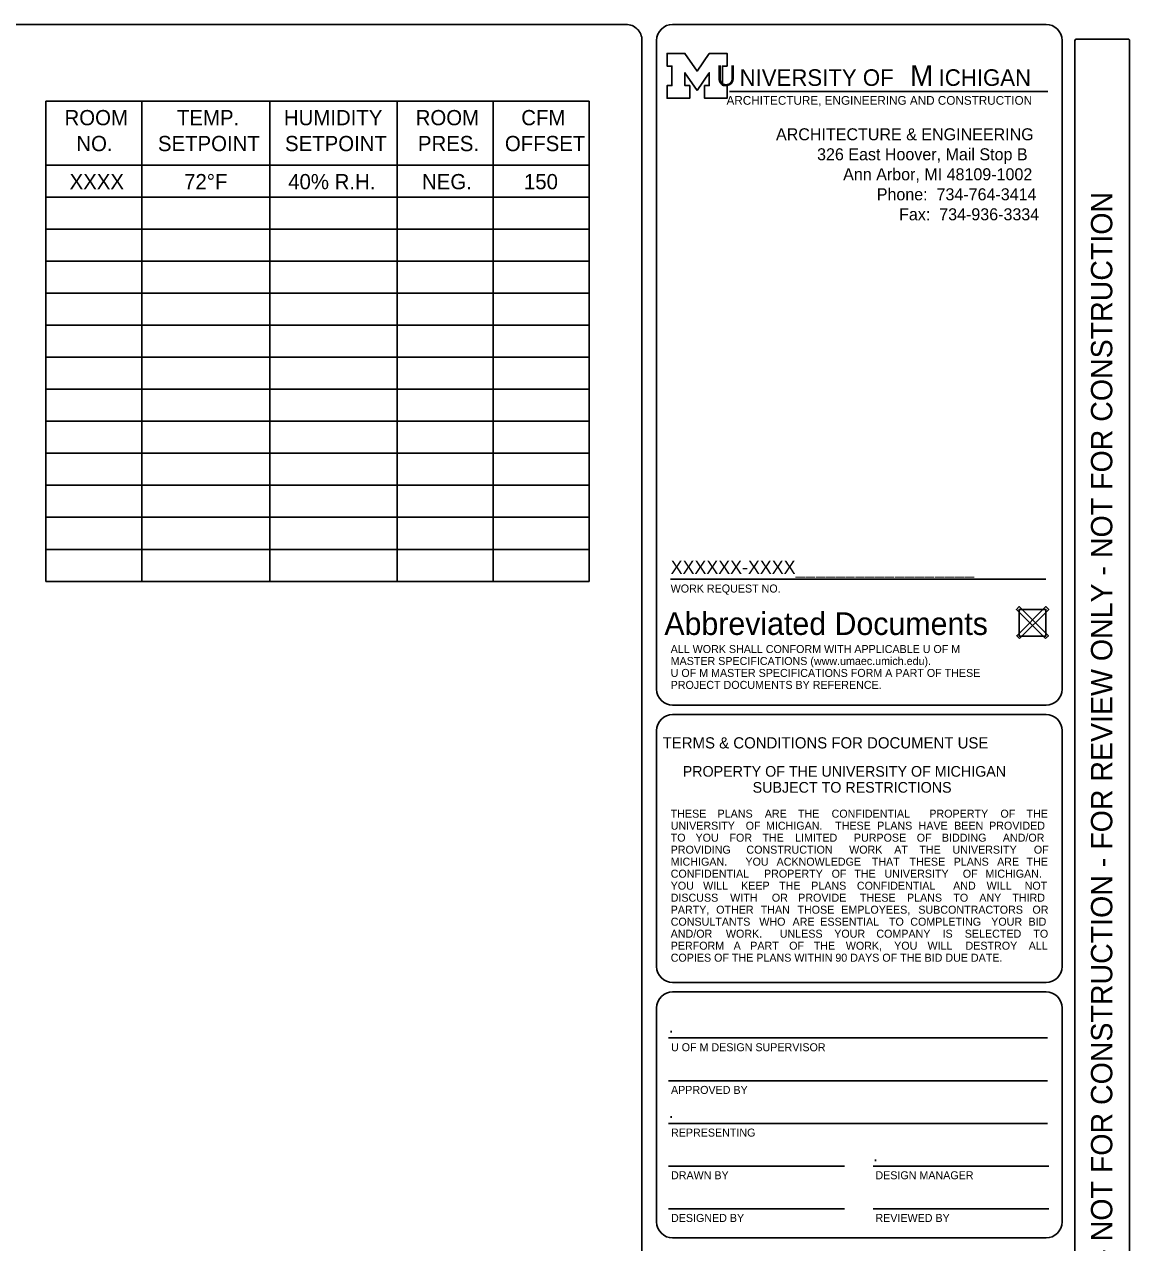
# Model space of a CAD drawing. Extents: x 0 to 567, y 1 to 184.
# Drawn here: x 498.1 to 567.1, y 107.6 to 183.7 of the extents above; entities that cross this region are included whole.
import ezdxf

# ---------------------------------------------------------------- set-up
doc = ezdxf.new("R2010")
doc.units = 0
for name, color, linetype in [('Default', 7, 'Continuous'), ('G-ANNO-CELL', 7, 'Continuous'), ('G-ANNO-LOGO', 7, 'Continuous'), ('G-ANNO-PROJ', 7, 'Continuous'), ('G-ANNO-PROJ (Construction)', 7, 'Continuous'), ('G-ANNO-TTLB', 7, 'Continuous'), ('G-DETL-LINE', 7, 'Continuous')]:
    doc.layers.add(name, color=color, linetype=linetype)

# ---------------------------------------------------------------- blocks, each defined once
blk = doc.blocks.new('POINT_DISPLAY')
at = {"layer": 'Default'}
blk.add_line((0, 0), (0, 0), dxfattribs=at)

msp = doc.modelspace()

# ---------------------------------------------------------------- linework, layer by layer
at = {"layer": 'G-ANNO-LOGO'}
for p, q in [((538.244, 181.132), (538.244, 181.923)), ((538.244, 181.923), (539.359, 181.923)), ((539.359, 181.923), (540.118, 180.822)), ((540.118, 180.822), (540.878, 181.923)), ((540.878, 181.923), (541.993, 181.923)), ((541.993, 181.923), (541.993, 181.132)), ((538.538, 181.132), (538.244, 181.132)), ((538.538, 179.908), (538.538, 181.132)), ((540.118, 179.614), (539.359, 180.714)), ((539.359, 180.714), (539.359, 179.908)), ((540.878, 180.714), (540.118, 179.614)), ((540.878, 179.908), (540.878, 180.714)), ((541.993, 181.132), (541.699, 181.132)), ((541.699, 181.132), (541.699, 179.936)), ((538.244, 179.118), (538.244, 179.908)), ((538.244, 179.908), (538.538, 179.908)), ((539.359, 179.908), (539.654, 179.908)), ((539.654, 179.908), (539.654, 179.118)), ((540.583, 179.118), (540.583, 179.908)), ((540.583, 179.908), (540.878, 179.908)), ((541.699, 179.936), (541.768, 179.908)), ((541.768, 179.908), (541.993, 179.908)), ((541.993, 179.908), (541.993, 179.118)), ((539.654, 179.118), (538.244, 179.118)), ((541.993, 179.118), (540.583, 179.118)), ((542.136, 179.549), (562.029, 179.549))]:
    msp.add_line(p, q, dxfattribs=at)
msp.add_lwpolyline([(540.118, 179.614), (539.359, 180.714), (539.359, 179.908), (539.654, 179.908), (539.654, 179.118), (538.244, 179.118), (538.244, 179.908), (538.538, 179.908), (538.538, 181.132), (538.244, 181.132), (538.244, 181.923), (539.359, 181.923), (540.118, 180.822), (540.878, 181.923), (541.993, 181.923), (541.993, 181.132), (541.699, 181.132), (541.699, 179.936), (541.768, 179.908), (541.993, 179.908), (541.993, 179.118), (540.583, 179.118), (540.583, 179.908), (540.878, 179.908), (540.878, 180.714)], close=True, dxfattribs=at)
at = {"layer": 'G-ANNO-PROJ'}
msp.add_line((561.911, 149.066), (538.463, 149.066), dxfattribs=at)
for points in [[(561.894, 145.354), (560.07, 147.178), (560.244, 147.352), (562.068, 145.528)], [(561.894, 145.354), (560.07, 147.178), (560.244, 147.352), (562.068, 145.528)], [(560.261, 145.354), (562.086, 147.178), (561.911, 147.352), (560.087, 145.528)], [(560.261, 145.354), (562.086, 147.178), (561.911, 147.352), (560.087, 145.528)], [(560.244, 145.511), (561.911, 145.511), (561.911, 147.178), (560.244, 147.178)]]:
    msp.add_lwpolyline(points, close=True, dxfattribs=at)
at = {"layer": 'G-ANNO-TTLB'}
for p, q in [((562.004, 120.398), (538.338, 120.398)), ((562.004, 117.731), (538.338, 117.731)), ((562.004, 115.064), (538.338, 115.064)), ((549.317, 112.398), (538.338, 112.398)), ((562.09, 112.398), (551.112, 112.398)), ((549.317, 109.731), (538.338, 109.731)), ((562.09, 109.731), (551.112, 109.731))]:
    msp.add_line(p, q, dxfattribs=at)
for points in [[(291.922, 183.734), (535.671, 183.735)], [(538.588, 183.737), (561.921, 183.737)], [(536.671, 182.735), (536.671, 2.735)], [(537.588, 142.191), (537.588, 182.737)], [(562.921, 182.737), (562.921, 142.191)], [(563.729, 2.735), (563.729, 182.734)], [(563.813, 182.818), (567.062, 182.818)], [(567.146, 182.735), (567.146, 2.735)], [(561.921, 141.191), (538.588, 141.191)], [(561.921, 140.608), (538.588, 140.608)], [(537.588, 139.608), (537.588, 124.861)], [(562.921, 124.861), (562.921, 139.608)], [(538.588, 123.861), (561.921, 123.861)], [(561.921, 123.278), (538.588, 123.278)], [(537.588, 122.278), (537.588, 108.904)], [(562.921, 108.904), (562.921, 122.278)], [(538.588, 107.904), (561.921, 107.904)]]:
    msp.add_lwpolyline(points, dxfattribs=at)
for centre, radius, start, end in [((535.671, 182.735), 1, 360, 90.00008), ((538.588, 182.737), 1, 90, 180), ((561.921, 182.737), 1, 0, 90), ((563.813, 182.734), 0.0833, 90.00008, 180), ((567.062, 182.735), 0.0833, 360, 90.00007), ((538.588, 142.191), 1, 180, 270), ((561.921, 142.191), 1, 270, 360), ((538.588, 139.608), 1, 90, 180), ((561.921, 139.608), 1, 360, 90), ((538.588, 124.861), 1, 180.00005, 270.00005), ((561.921, 124.861), 1, 270.00005, 0.00005), ((538.588, 122.278), 1, 90, 180), ((561.921, 122.278), 1, 360, 90), ((538.588, 108.904), 1, 180.00005, 270.00005), ((561.921, 108.904), 1, 270.00005, 0.00005)]:
    msp.add_arc(centre, radius, start, end, dxfattribs=at)
at = {"layer": 'G-DETL-LINE'}
for p, q in [((499.423, 178.933), (533.367, 178.933)), ((499.423, 178.933), (499.423, 148.933)), ((505.423, 178.933), (505.423, 148.933)), ((513.423, 178.933), (513.423, 148.933)), ((521.367, 178.933), (521.367, 148.933)), ((527.367, 178.933), (527.367, 148.933)), ((533.367, 178.933), (533.367, 148.933)), ((499.423, 174.933), (521.367, 174.933)), ((521.367, 174.933), (533.367, 174.933)), ((499.423, 172.933), (521.367, 172.933)), ((521.367, 172.933), (533.367, 172.933)), ((499.423, 170.933), (521.367, 170.933)), ((521.367, 170.933), (533.367, 170.933)), ((499.423, 168.933), (521.367, 168.933)), ((521.367, 168.933), (533.367, 168.933)), ((499.423, 166.933), (521.367, 166.933)), ((521.367, 166.933), (533.367, 166.933)), ((499.423, 164.933), (521.367, 164.933)), ((521.367, 164.933), (533.367, 164.933)), ((499.423, 162.933), (521.367, 162.933)), ((521.367, 162.933), (533.367, 162.933)), ((499.423, 160.933), (521.367, 160.933)), ((521.367, 160.933), (533.367, 160.933)), ((499.423, 158.933), (521.367, 158.933)), ((521.367, 158.933), (533.367, 158.933)), ((499.423, 156.933), (521.367, 156.933)), ((521.367, 156.933), (533.367, 156.933)), ((499.423, 154.933), (521.367, 154.933)), ((521.367, 154.933), (533.367, 154.933)), ((499.423, 152.933), (521.367, 152.933)), ((521.367, 152.933), (533.367, 152.933)), ((499.423, 150.933), (521.367, 150.933)), ((521.367, 150.933), (533.367, 150.933)), ((499.423, 148.933), (533.367, 148.933))]:
    msp.add_line(p, q, dxfattribs=at)

# ---------------------------------------------------------------- block references
at = {"layer": 'G-ANNO-PROJ (Construction)'}
msp.add_blockref('POINT_DISPLAY', (538.531, 149.066), dxfattribs=at)

# ---------------------------------------------------------------- texts
at = {"layer": 'G-ANNO-CELL'}
msp.add_text('FOR REVIEW ONLY - NOT FOR CONSTRUCTION - FOR REVIEW ONLY - NOT FOR CONSTRUCTION - FOR REVIEW ONLY - NOT FOR CONSTRUCTION - FOR REVIEW ONLY - NOT FOR CONSTRUCTION', height=1.333333, rotation=90, dxfattribs=at).set_placement((566.063, 4.083))
at = {"layer": 'G-ANNO-LOGO'}
for s, height, p in [('U', 1.285, (541.31, 179.893)), ('NIVERSITY OF', 1.03676, (542.77, 179.893)), ('M', 1.285, (553.433, 179.893)), ('ICHIGAN', 1.0368, (555.208, 179.893)), ('ARCHITECTURE, ENGINEERING AND CONSTRUCTION', 0.54688, (541.955, 178.713)), ('ARCHITECTURE & ENGINEERING', 0.75, (545.046, 176.493)), ('326 East Hoover, Mail Stop B', 0.75, (547.613, 175.243)), ('Ann Arbor, MI 48109-1002', 0.75, (549.243, 173.993)), ('Phone:  734-764-3414', 0.75, (551.343, 172.743)), ('Fax:  734-936-3334', 0.75, (552.739, 171.493))]:
    msp.add_text(s, height=height, dxfattribs=at).set_placement(p)
at = {"layer": 'G-ANNO-PROJ'}
for s, height, p in [('XXXXXX-XXXX__________________', 0.83332, (538.463, 149.399)), ('WORK REQUEST NO.', 0.5, (538.463, 148.233)), ('Abbreviated Documents', 1.41667, (538.069, 145.582)), ('ALL WORK SHALL CONFORM WITH APPLICABLE U OF M ', 0.5, (538.463, 144.453)), ('MASTER SPECIFICATIONS (www.umaec.umich.edu).', 0.5, (538.463, 143.706)), ('U OF M MASTER SPECIFICATIONS FORM A PART OF THESE ', 0.5, (538.463, 142.959)), ('PROJECT DOCUMENTS BY REFERENCE.', 0.5, (538.463, 142.212)), ('TERMS & CONDITIONS FOR DOCUMENT USE', 0.69894, (537.963, 138.491)), ('PROPERTY OF THE UNIVERSITY OF MICHIGAN ', 0.66667, (539.216, 136.726)), ('SUBJECT TO RESTRICTIONS', 0.66667, (543.586, 135.726)), ('THESE ', 0.5, (538.465, 134.165)), ('PLANS ', 0.5, (541.396, 134.165)), ('ARE ', 0.5, (544.346, 134.165)), ('THE ', 0.5, (546.42, 134.165)), ('CONFIDENTIAL ', 0.5, (548.52, 134.165)), ('PROPERTY ', 0.5, (554.628, 134.165)), ('OF ', 0.5, (559.072, 134.165)), ('THE ', 0.5, (560.703, 134.165)), ('UNIVERSITY ', 0.5, (538.465, 133.415)), ('OF ', 0.5, (543.152, 133.415)), ('MICHIGAN. ', 0.5, (544.421, 133.415)), ('THESE ', 0.5, (548.741, 133.415)), ('PLANS ', 0.5, (551.372, 133.415)), ('HAVE ', 0.5, (553.958, 133.415)), ('BEEN ', 0.5, (556.179, 133.415)), ('PROVIDED ', 0.5, (558.363, 133.415)), ('TO ', 0.5, (538.465, 132.665)), ('YOU ', 0.5, (540.016, 132.665)), ('FOR ', 0.5, (542.138, 132.665)), ('THE ', 0.5, (544.197, 132.665)), ('LIMITED ', 0.5, (546.237, 132.665)), ('PURPOSE ', 0.5, (549.913, 132.665)), ('OF ', 0.5, (553.842, 132.665)), ('BIDDING ', 0.5, (555.413, 132.665)), ('AND/OR ', 0.5, (559.22, 132.665)), ('PROVIDING ', 0.5, (538.465, 131.915)), ('CONSTRUCTION ', 0.5, (543.197, 131.915)), ('WORK ', 0.5, (549.616, 131.915)), ('AT ', 0.5, (552.435, 131.915)), ('THE ', 0.5, (554.005, 131.915)), ('UNIVERSITY ', 0.5, (556.076, 131.915)), ('OF ', 0.5, (561.159, 131.915)), ('MICHIGAN. ', 0.5, (538.465, 131.165)), ('YOU ', 0.5, (543.136, 131.165)), ('ACKNOWLEDGE ', 0.5, (545.084, 131.165)), ('THAT ', 0.5, (551.033, 131.165)), ('THESE ', 0.5, (553.389, 131.165)), ('PLANS ', 0.5, (556.149, 131.165)), ('ARE ', 0.5, (558.864, 131.165)), ('THE ', 0.5, (560.703, 131.165)), ('CONFIDENTIAL ', 0.5, (538.465, 130.415)), ('PROPERTY ', 0.5, (544.295, 130.415)), ('OF ', 0.5, (548.522, 130.415)), ('THE ', 0.5, (549.938, 130.415)), ('UNIVERSITY ', 0.5, (551.822, 130.415)), ('OF ', 0.5, (556.719, 130.415)), ('MICHIGAN. ', 0.5, (558.134, 130.415)), ('YOU ', 0.5, (538.465, 129.665)), ('DISCUSS ', 0.5, (538.465, 128.915)), ('WILL ', 0.5, (540.491, 129.665)), ('WITH ', 0.5, (542.184, 128.915)), ('KEEP ', 0.5, (542.868, 129.665)), ('OR ', 0.5, (544.785, 128.915)), ('THE ', 0.5, (545.24, 129.665)), ('PROVIDE ', 0.5, (546.432, 128.915)), ('PLANS ', 0.5, (547.246, 129.665)), ('CONFIDENTIAL ', 0.5, (550.101, 129.665)), ('THESE ', 0.5, (550.29, 128.915)), ('PLANS ', 0.5, (553.231, 128.915)), ('AND ', 0.5, (556.116, 129.665)), ('TO ', 0.5, (556.128, 128.915)), ('ANY ', 0.5, (557.75, 128.915)), ('WILL ', 0.5, (558.208, 129.665)), ('THIRD ', 0.5, (559.814, 128.915)), ('NOT ', 0.5, (560.585, 129.665)), ('PARTY, ', 0.5, (538.465, 128.165)), ('OTHER ', 0.5, (541.308, 128.165)), ('THAN ', 0.5, (544.092, 128.165)), ('THOSE ', 0.5, (546.386, 128.165)), ('EMPLOYEES, ', 0.5, (549.126, 128.165)), ('SUBCONTRACTORS ', 0.5, (553.94, 128.165)), ('OR ', 0.5, (561.071, 128.165)), ('CONSULTANTS ', 0.5, (538.465, 127.415)), ('WHO ', 0.5, (544.002, 127.415)), ('ARE ', 0.5, (546.081, 127.415)), ('ESSENTIAL ', 0.5, (547.813, 127.415)), ('TO ', 0.5, (552.104, 127.415)), ('COMPLETING ', 0.5, (553.438, 127.415)), ('YOUR ', 0.5, (558.495, 127.415)), ('BID ', 0.5, (560.826, 127.415)), ('AND/OR ', 0.5, (538.465, 126.665)), ('WORK. ', 0.5, (541.915, 126.665)), ('UNLESS ', 0.5, (545.282, 126.665)), ('YOUR ', 0.5, (548.684, 126.665)), ('COMPANY ', 0.5, (551.318, 126.665)), ('IS ', 0.5, (555.455, 126.665)), ('SELECTED ', 0.5, (556.843, 126.665)), ('TO ', 0.5, (561.129, 126.665)), ('PERFORM ', 0.5, (538.465, 125.915)), ('A ', 0.5, (542.398, 125.915)), ('PART ', 0.5, (543.437, 125.915)), ('OF ', 0.5, (545.87, 125.915)), ('THE ', 0.5, (547.405, 125.915)), ('WORK, ', 0.5, (549.408, 125.915)), ('YOU ', 0.5, (552.43, 125.915)), ('WILL ', 0.5, (554.516, 125.915)), ('DESTROY ', 0.5, (556.89, 125.915)), ('ALL ', 0.5, (560.838, 125.915)), ('COPIES OF THE PLANS WITHIN 90 DAYS OF THE BID DUE DATE.', 0.5, (538.465, 125.165)), ('.', 0.833, (538.338, 120.731)), ('.', 0.833, (538.338, 115.398)), ('.', 0.833, (551.112, 112.686))]:
    msp.add_text(s, height=height, dxfattribs=at).set_placement(p)
at = {"layer": 'G-ANNO-TTLB'}
for s, p in [('U OF M DESIGN SUPERVISOR', (538.485, 119.57)), ('APPROVED BY', (538.485, 116.903)), ('REPRESENTING', (538.485, 114.237)), ('DRAWN BY', (538.485, 111.57)), ('DESIGN MANAGER', (551.259, 111.57)), ('DESIGNED BY', (538.485, 108.903)), ('REVIEWED BY', (551.259, 108.903))]:
    msp.add_text(s, height=0.5, dxfattribs=at).set_placement(p)
at = {"layer": 'G-DETL-LINE'}
for s, p in [('ROOM', (500.585, 177.433)), ('TEMP.', (507.61, 177.433)), ('HUMIDITY', (514.294, 177.433)), ('ROOM', (522.529, 177.433)), ('CFM', (529.127, 177.433)), ('NO.', (501.324, 175.814)), ('SETPOINT', (506.42, 175.814)), ('SETPOINT', (514.363, 175.814)), ('PRES.', (522.669, 175.814)), ('OFFSET', (528.105, 175.814)), ('XXXX', (500.902, 173.433)), ('72%%DF', (508.058, 173.433)), ('40%%% R.H.', (514.562, 173.433)), ('NEG.', (522.927, 173.433)), ('150', (529.294, 173.433))]:
    msp.add_text(s, height=0.9523, dxfattribs=at).set_placement(p)

doc.saveas('drawing.dxf')
